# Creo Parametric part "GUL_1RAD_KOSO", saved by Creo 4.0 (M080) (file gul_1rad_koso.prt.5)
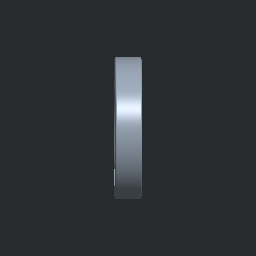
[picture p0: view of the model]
Units: Custom; MM, KILOGRAM, SECS
Materials in the file: STAHL, OCEL_N

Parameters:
  BEZEICHNUNG = "LOZISKO S KOSOUHLYM STYKOM"
  KATEGORIE = "4"
  NAZOV = "LOZISKO S KOSOUHLYM STYKOM"
  NORMA = "STN 02 4645"
  PTC_MATERIAL_NAME = "STAHL"

Other parameters: HMOTNOST, D4, D9, D2, D3, D7, D8, D6, D12, D43, D44, D63, D64

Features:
  1. datum plane "KF1"
  2. datum plane "DTM2"
  3. datum plane "DTM3"
  4. protrusion
  5. cut
  6. round
  7. round
  8. pattern
  9. datum plane "DTM4"
  10. protrusion
  11. protrusion
  12. protrusion
  13. protrusion
  14. protrusion
  15. protrusion
  16. protrusion
  17. protrusion
  18. protrusion
  19. protrusion
  20. protrusion
  21. protrusion
  22. protrusion
  23. protrusion
  24. protrusion
  25. protrusion
  26. protrusion
  27. protrusion

Other named items: MA1

Named dimensions: r_1s, r_3s

Layers: NORMTEILE

Family table entries: GENERIC, 024646-7200B, GUL_1RAD_KOSO, value(d_val), 2/>, 2/", value(s_val), LOZISKO-7200 , value(i_val), 024646-7201B, GUL_1RAD_KOSO, !/(, 2/@, 2/$, "LOZISKO-7201 , 024646-7301B, GUL_1RAD_KOSO, !/(, 2/(, "LOZISKO-7301 , 024646-7202B, GUL_1RAD_KOSO, !/., 2/&, "LOZISKO-7202 , 024646-7302B, GUL_1RAD_KOSO, !/., 2/E, 2/*, "LOZISKO-7302 , 024646-7203B, GUL_1RAD_KOSO, !/1, 2/D, 2/(, "LOZISKO-7203 , 024646-7303B, GUL_1RAD_KOSO, !/1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

Surfaces: 20 torus, 12 cylinder, 2 plane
